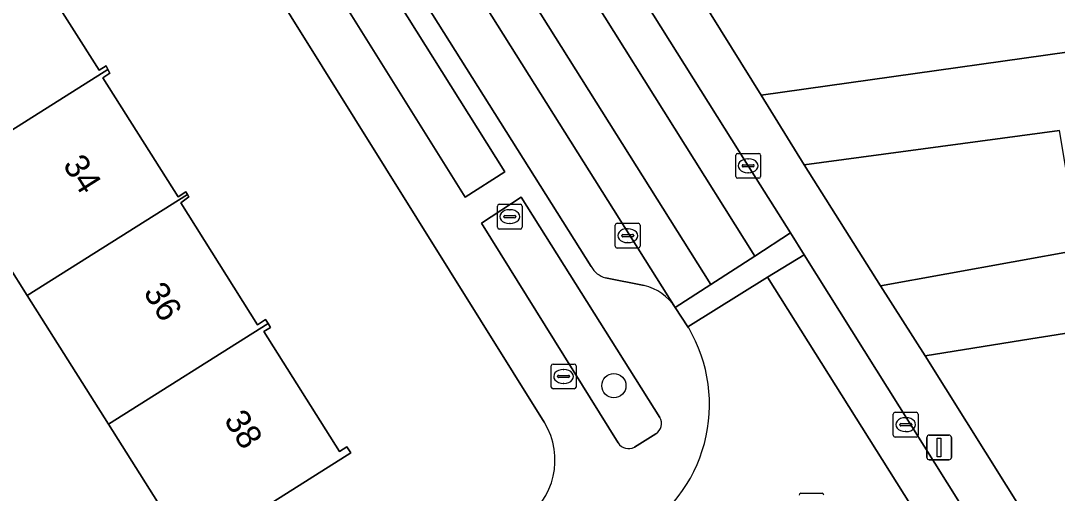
# Model space of a CAD drawing. Extents: x 160077 to 160948, y 386481 to 387498.
# Drawn here: x 160424.4 to 160466.22, y 387013.92 to 387032.98 of the extents above; entities that cross this region are included whole.
import ezdxf

# ---------------------------------------------------------------- set-up
doc = ezdxf.new("R2010")
doc.units = 0
for name, color, linetype in [('IMGEO_Boom', 7, 'Continuous'), ('IMGEO_Brandkraan', 7, 'Continuous'), ('IMGEO_Erf', 7, 'Continuous'), ('IMGEO_Groenvoorziening', 7, 'Continuous'), ('IMGEO_Kolk', 7, 'Continuous'), ('IMGEO_Lichtmast', 7, 'Continuous'), ('IMGEO_Pand', 7, 'Continuous'), ('IMGEO_Pand_nummerreeks', 7, 'Continuous'), ('IMGEO_Parkeervlak_open', 7, 'Continuous'), ('IMGEO_Rijbaan_lokaal_gesloten', 7, 'Continuous'), ('IMGEO_Rijbaan_lokaal_open', 7, 'Continuous'), ('IMGEO_Rioolput', 7, 'Continuous'), ('IMGEO_Voetpad_open', 7, 'Continuous')]:
    doc.layers.add(name, color=color, linetype=linetype)

msp = doc.modelspace()

# ---------------------------------------------------------------- linework, layer by layer
at = {"layer": 'IMGEO_Boom'}
msp.add_circle((160448.328, 387018.258), 0.489, dxfattribs=at)
at = {"layer": 'IMGEO_Brandkraan'}
for p, q in [((160445.799, 387018.204), (160445.799, 387019.056)), ((160445.874, 387019.13), (160446.726, 387019.13)), ((160446.287, 387018.91), (160446.312, 387018.91)), ((160446.8, 387019.056), (160446.8, 387018.204)), ((160446.058, 387018.624), (160446.058, 387018.636)), ((160446.496, 387018.587), (160446.098, 387018.587)), ((160446.101, 387018.673), (160446.499, 387018.673)), ((160446.542, 387018.636), (160446.542, 387018.624)), ((160446.726, 387018.13), (160445.874, 387018.13)), ((160446.31, 387018.35), (160446.285, 387018.35))]:
    msp.add_line(p, q, dxfattribs=at)
for points in [[(160445.799, 387018.204), (160445.799, 387019.056)], [(160445.874, 387019.13), (160446.726, 387019.13)], [(160446.8, 387019.056), (160446.8, 387018.204)], [(160446.726, 387018.13), (160445.874, 387018.13)]]:
    msp.add_lwpolyline(points, dxfattribs=at)
for centre, radius, start, end in [((160445.876, 387019.054), 0.0765, 91.552, 178.448), ((160445.876, 387019.054), 0.0765, 91.552, 178.448), ((160446.724, 387019.054), 0.0765, 1.552, 88.448), ((160446.724, 387019.054), 0.0765, 1.552, 88.448), ((160446.098, 387018.633), 0.0403, 85.8775, 175.7526), ((160446.095, 387018.623), 0.0366, 178.938, 274.7102), ((160446.499, 387018.63), 0.043, 264.8664, 352.4533), ((160446.503, 387018.635), 0.0386, 1.7309, 96.639), ((160445.876, 387018.206), 0.0765, 181.552, 268.448), ((160445.876, 387018.206), 0.0765, 181.552, 268.448), ((160446.724, 387018.206), 0.0765, 271.552, 358.448), ((160446.724, 387018.206), 0.0765, 271.552, 358.448)]:
    msp.add_arc(centre, radius, start, end, dxfattribs=at)
for centre, major_axis, ratio, start_param, end_param in [((160446.286, 387018.63), (-0.387, 0.002), 0.722429, 4.712389, 7.853982), ((160446.311, 387018.63), (-0.39, 0.002), 0.717154, 1.570796, 4.712389)]:
    msp.add_ellipse(centre, major_axis=major_axis, ratio=ratio, start_param=start_param, end_param=end_param, dxfattribs=at)
at = {"layer": 'IMGEO_Erf'}
for points in [[(160436.293, 387058.867), (160454.264, 387029.968), (160471.096, 387032.344), (160516.497, 387039.629), (160514.932, 387049.194), (160513.761, 387056.353), (160520.499, 387057.388)], [(160445.527, 387016.772), (160445.519, 387016.785), (160423.783, 387051.6)], [(160424.447, 387035.907), (160427.556, 387030.979), (160427.84, 387031.158), (160427.914, 387031.009), (160427.989, 387030.859), (160427.713, 387030.674), (160430.743, 387025.872), (160431.058, 387026.07), (160431.119, 387025.971), (160431.178, 387025.874), (160430.851, 387025.634), (160433.953, 387020.718), (160434.276, 387020.922), (160434.375, 387020.765), (160434.473, 387020.61), (160434.202, 387020.439), (160437.253, 387015.604), (160437.555, 387015.794), (160437.712, 387015.544), (160431.243, 387011.463), (160427.937, 387016.702), (160424.66, 387021.895), (160421.473, 387026.944)]]:
    msp.add_lwpolyline(points, dxfattribs=at)
msp.add_arc((160443.038, 387015.255), 2.915, 302.8254, 31.3564, dxfattribs=at)
at = {"layer": 'IMGEO_Groenvoorziening'}
for points in [[(160438.184, 387036.037), (160436.613, 387035.011), (160442.33, 387025.857), (160443.932, 387026.885)], [(160466.313, 387028.547), (160456.003, 387027.165), (160459.086, 387022.289), (160467.115, 387023.735)]]:
    msp.add_lwpolyline(points, close=True, dxfattribs=at)
for points in [[(160536.126, 387031.222), (160522.827, 387029.176), (160500, 387025.661), (160465.147, 387020.143), (160460.883, 387019.457), (160464.986, 387012.914)], [(160444.582, 387025.864), (160442.985, 387024.818), (160448.503, 387015.949)], [(160450.181, 387016.975), (160444.582, 387025.864)], [(160449.155, 387015.781), (160450.02, 387016.321)]]:
    msp.add_lwpolyline(points, dxfattribs=at)
for centre, radius, start, end in [((160449.782, 387016.726), 0.47, 300.4166, 31.9236), ((160448.917, 387016.205), 0.487, 211.7671, 299.3349)]:
    msp.add_arc(centre, radius, start, end, dxfattribs=at)
at = {"layer": 'IMGEO_Kolk'}
for p, q in [((160453.247, 387026.699), (160453.247, 387027.551)), ((160453.322, 387027.625), (160454.174, 387027.625)), ((160453.735, 387027.405), (160453.76, 387027.405)), ((160454.248, 387027.551), (160454.248, 387026.699)), ((160453.506, 387027.119), (160453.506, 387027.131)), ((160453.944, 387027.082), (160453.546, 387027.082)), ((160453.549, 387027.168), (160453.947, 387027.168)), ((160453.99, 387027.131), (160453.99, 387027.119)), ((160454.174, 387026.625), (160453.322, 387026.625)), ((160453.758, 387026.845), (160453.733, 387026.845)), ((160443.627, 387024.65), (160443.627, 387025.502)), ((160443.702, 387025.576), (160444.554, 387025.576)), ((160444.115, 387025.356), (160444.14, 387025.356)), ((160444.628, 387025.502), (160444.628, 387024.65)), ((160443.886, 387025.07), (160443.886, 387025.082)), ((160444.324, 387025.033), (160443.926, 387025.033)), ((160443.929, 387025.119), (160444.327, 387025.119)), ((160444.138, 387024.796), (160444.113, 387024.796)), ((160444.37, 387025.082), (160444.37, 387025.07)), ((160448.461, 387024.807), (160449.313, 387024.807)), ((160444.554, 387024.576), (160443.702, 387024.576)), ((160448.386, 387023.881), (160448.386, 387024.733)), ((160448.688, 387024.35), (160449.086, 387024.35)), ((160448.874, 387024.587), (160448.899, 387024.587)), ((160449.387, 387024.733), (160449.387, 387023.881)), ((160448.645, 387024.301), (160448.645, 387024.313)), ((160449.083, 387024.264), (160448.685, 387024.264)), ((160448.897, 387024.027), (160448.872, 387024.027)), ((160449.129, 387024.313), (160449.129, 387024.301)), ((160449.313, 387023.807), (160448.461, 387023.807)), ((160459.601, 387016.26), (160459.601, 387017.112)), ((160459.676, 387017.186), (160460.528, 387017.186)), ((160460.089, 387016.966), (160460.114, 387016.966)), ((160460.602, 387017.112), (160460.602, 387016.26)), ((160459.86, 387016.68), (160459.86, 387016.692)), ((160460.298, 387016.643), (160459.9, 387016.643)), ((160459.903, 387016.729), (160460.301, 387016.729)), ((160460.112, 387016.406), (160460.087, 387016.406)), ((160460.344, 387016.692), (160460.344, 387016.68)), ((160460.528, 387016.186), (160459.676, 387016.186))]:
    msp.add_line(p, q, dxfattribs=at)
for points in [[(160453.247, 387026.699), (160453.247, 387027.551)], [(160453.322, 387027.625), (160454.174, 387027.625)], [(160454.248, 387027.551), (160454.248, 387026.699)], [(160454.174, 387026.625), (160453.322, 387026.625)], [(160443.627, 387024.65), (160443.627, 387025.502)], [(160443.702, 387025.576), (160444.554, 387025.576)], [(160444.628, 387025.502), (160444.628, 387024.65)], [(160448.461, 387024.807), (160449.313, 387024.807)], [(160444.554, 387024.576), (160443.702, 387024.576)], [(160448.386, 387023.881), (160448.386, 387024.733)], [(160449.387, 387024.733), (160449.387, 387023.881)], [(160449.313, 387023.807), (160448.461, 387023.807)], [(160459.601, 387016.26), (160459.601, 387017.112)], [(160459.676, 387017.186), (160460.528, 387017.186)], [(160460.602, 387017.112), (160460.602, 387016.26)], [(160460.528, 387016.186), (160459.676, 387016.186)]]:
    msp.add_lwpolyline(points, dxfattribs=at)
for centre, radius, start, end in [((160453.324, 387027.549), 0.0765, 91.552, 178.448), ((160453.324, 387027.549), 0.0765, 91.552, 178.448), ((160454.172, 387027.549), 0.0765, 1.552, 88.448), ((160454.172, 387027.549), 0.0765, 1.552, 88.448), ((160453.546, 387027.128), 0.0403, 85.8775, 175.7526), ((160453.543, 387027.118), 0.0366, 178.938, 274.7102), ((160453.947, 387027.125), 0.043, 264.8664, 352.4533), ((160453.951, 387027.13), 0.0386, 1.7309, 96.639), ((160453.324, 387026.701), 0.0765, 181.552, 268.448), ((160453.324, 387026.701), 0.0765, 181.552, 268.448), ((160454.172, 387026.701), 0.0765, 271.552, 358.448), ((160454.172, 387026.701), 0.0765, 271.552, 358.448), ((160443.704, 387025.5), 0.0765, 91.552, 178.448), ((160443.704, 387025.5), 0.0765, 91.552, 178.448), ((160444.552, 387025.5), 0.0765, 1.552, 88.448), ((160444.552, 387025.5), 0.0765, 1.552, 88.448), ((160443.926, 387025.079), 0.0403, 85.8775, 175.7526), ((160443.923, 387025.069), 0.0366, 178.938, 274.7102), ((160444.327, 387025.076), 0.043, 264.8664, 352.4533), ((160444.331, 387025.081), 0.0386, 1.7309, 96.639), ((160448.463, 387024.731), 0.0765, 91.552, 178.448), ((160448.463, 387024.731), 0.0765, 91.552, 178.448), ((160449.311, 387024.731), 0.0765, 1.552, 88.448), ((160449.311, 387024.731), 0.0765, 1.552, 88.448), ((160443.704, 387024.652), 0.0765, 181.552, 268.448), ((160443.704, 387024.652), 0.0765, 181.552, 268.448), ((160444.552, 387024.652), 0.0765, 271.552, 358.448), ((160444.552, 387024.652), 0.0765, 271.552, 358.448), ((160448.685, 387024.31), 0.0403, 85.8775, 175.7526), ((160449.09, 387024.312), 0.0386, 1.7309, 96.639), ((160448.682, 387024.3), 0.0366, 178.938, 274.7102), ((160449.086, 387024.307), 0.043, 264.8664, 352.4533), ((160448.463, 387023.883), 0.0765, 181.552, 268.448), ((160448.463, 387023.883), 0.0765, 181.552, 268.448), ((160449.311, 387023.883), 0.0765, 271.552, 358.448), ((160449.311, 387023.883), 0.0765, 271.552, 358.448), ((160459.678, 387017.11), 0.0765, 91.552, 178.448), ((160459.678, 387017.11), 0.0765, 91.552, 178.448), ((160460.526, 387017.11), 0.0765, 1.552, 88.448), ((160460.526, 387017.11), 0.0765, 1.552, 88.448), ((160459.9, 387016.689), 0.0403, 85.8775, 175.7526), ((160459.897, 387016.679), 0.0366, 178.938, 274.7102), ((160460.301, 387016.686), 0.043, 264.8664, 352.4533), ((160460.305, 387016.691), 0.0386, 1.7309, 96.639), ((160459.678, 387016.262), 0.0765, 181.552, 268.448), ((160459.678, 387016.262), 0.0765, 181.552, 268.448), ((160460.526, 387016.262), 0.0765, 271.552, 358.448), ((160460.526, 387016.262), 0.0765, 271.552, 358.448)]:
    msp.add_arc(centre, radius, start, end, dxfattribs=at)
for centre, major_axis, ratio, start_param, end_param in [((160453.734, 387027.125), (-0.387, 0.002), 0.722429, 4.712389, 7.853982), ((160453.759, 387027.125), (-0.39, 0.002), 0.717154, 1.570796, 4.712389), ((160444.114, 387025.076), (-0.387, 0.002), 0.722429, 4.712389, 7.853982), ((160444.139, 387025.076), (-0.39, 0.002), 0.717154, 1.570796, 4.712389), ((160448.873, 387024.307), (-0.387, 0.002), 0.722429, 4.712389, 7.853982), ((160448.898, 387024.307), (-0.39, 0.002), 0.717154, 1.570796, 4.712389), ((160460.088, 387016.686), (-0.387, 0.002), 0.722429, 4.712389, 7.853982), ((160460.113, 387016.686), (-0.39, 0.002), 0.717154, 1.570796, 4.712389)]:
    msp.add_ellipse(centre, major_axis=major_axis, ratio=ratio, start_param=start_param, end_param=end_param, dxfattribs=at)
at = {"layer": 'IMGEO_Lichtmast'}
for p, q in [((160460.954, 387015.366), (160460.954, 387016.166)), ((160460.954, 387016.166), (160460.954, 387015.366)), ((160461.054, 387016.266), (160461.844, 387016.266)), ((160461.844, 387016.266), (160461.054, 387016.266)), ((160461.944, 387016.166), (160461.944, 387015.366)), ((160461.944, 387015.366), (160461.944, 387016.166)), ((160461.844, 387015.266), (160461.054, 387015.266)), ((160461.054, 387015.266), (160461.844, 387015.266))]:
    msp.add_line(p, q, dxfattribs=at)
msp.add_lwpolyline([(160461.374, 387016.141), (160461.524, 387016.141), (160461.524, 387015.391), (160461.374, 387015.391), (160461.374, 387016.141)], dxfattribs=at)
for centre, start, end in [((160461.054, 387016.166), 90, 180), ((160461.054, 387016.166), 90, 180), ((160461.844, 387016.166), 0, 90), ((160461.844, 387016.166), 360, 90), ((160461.054, 387015.366), 180, 270), ((160461.054, 387015.366), 180, 270), ((160461.844, 387015.366), 270, 0), ((160461.844, 387015.366), 270, 0)]:
    msp.add_arc(centre, 0.1, start, end, dxfattribs=at)
at = {"layer": 'IMGEO_Pand'}
for points in [[(160418.212, 387032.112), (160421.473, 387026.944), (160427.914, 387031.009), (160427.84, 387031.158), (160427.556, 387030.979), (160424.447, 387035.907), (160424.705, 387036.07), (160424.642, 387036.17)], [(160431.119, 387025.971), (160431.058, 387026.07), (160430.743, 387025.872), (160427.713, 387030.674), (160427.989, 387030.859), (160427.914, 387031.009), (160421.473, 387026.944), (160424.66, 387021.895)], [(160434.375, 387020.765), (160434.276, 387020.922), (160433.953, 387020.718), (160430.851, 387025.634), (160431.178, 387025.874), (160431.119, 387025.971), (160424.66, 387021.895), (160427.937, 387016.702)], [(160427.937, 387016.702), (160431.243, 387011.463), (160437.712, 387015.544), (160437.555, 387015.794), (160437.253, 387015.604), (160434.202, 387020.439), (160434.473, 387020.61), (160434.375, 387020.765)]]:
    msp.add_lwpolyline(points, close=True, dxfattribs=at)
at = {"layer": 'IMGEO_Parkeervlak_open'}
for points in [[(160450.802, 387021.407), (160429.818, 387054.758)], [(160429.809, 387051.026), (160447.411, 387023.059)], [(160447.989, 387022.61), (160449.549, 387022.299)]]:
    msp.add_lwpolyline(points, dxfattribs=at)
for centre, radius, start, end in [((160448.226, 387023.511), 0.932, 209.0415, 255.2772), ((160449.063, 387020.29), 2.067, 32.71, 76.3965)]:
    msp.add_arc(centre, radius, start, end, dxfattribs=at)
at = {"layer": 'IMGEO_Rijbaan_lokaal_gesloten'}
for points in [[(160416.063, 387087.072), (160406.823, 387101.852), (160398.089, 387115.794), (160388.289, 387131.421), (160386.556, 387134.162), (160385.146, 387133.284), (160405.388, 387100.925), (160454.017, 387023.48), (160455.457, 387024.416), (160453.748, 387027.125), (160445.805, 387039.762), (160436.736, 387054.149), (160431.311, 387062.749), (160427.037, 387069.523), (160425.845, 387071.435)], [(160383.315, 387132.149), (160381.898, 387131.264), (160382.171, 387130.783), (160398.645, 387104.519), (160401.279, 387100.695), (160425.761, 387061.225), (160426.837, 387059.5), (160429.508, 387055.263), (160429.818, 387054.758), (160450.802, 387021.407), (160452.236, 387022.341), (160427.331, 387061.943), (160402.73, 387101.168), (160393.07, 387116.568)], [(160454.532, 387022.633), (160456.003, 387023.539), (160455.457, 387024.416), (160454.017, 387023.48), (160452.236, 387022.341), (160450.802, 387021.407), (160451.315, 387020.631)], [(160456.003, 387023.539), (160454.532, 387022.633), (160464.671, 387006.514), (160466.121, 387007.413)]]:
    msp.add_lwpolyline(points, close=True, dxfattribs=at)
at = {"layer": 'IMGEO_Rijbaan_lokaal_open'}
msp.add_lwpolyline([(160405.388, 387100.925), (160385.146, 387133.284), (160383.315, 387132.149), (160393.07, 387116.568), (160402.73, 387101.168), (160427.331, 387061.943), (160452.236, 387022.341), (160454.017, 387023.48)], close=True, dxfattribs=at)
for points in [[(160454.532, 387022.633), (160451.315, 387020.631), (160451.345, 387020.586)], [(160461.463, 387004.46), (160464.671, 387006.514), (160454.532, 387022.633)]]:
    msp.add_lwpolyline(points, dxfattribs=at)
msp.add_arc((160446.083, 387017.498), 6.102, 299.8554, 30.4053, dxfattribs=at)
at = {"layer": 'IMGEO_Rioolput'}
msp.add_line((160455.874, 387013.918), (160456.726, 387013.918), dxfattribs=at)
msp.add_lwpolyline([(160455.874, 387013.918), (160456.726, 387013.918)], dxfattribs=at)
for centre, start, end in [((160455.876, 387013.842), 91.552, 178.448), ((160455.876, 387013.842), 91.552, 178.448), ((160456.724, 387013.842), 1.552, 88.448), ((160456.724, 387013.842), 1.552, 88.448)]:
    msp.add_arc(centre, 0.0765, start, end, dxfattribs=at)
at = {"layer": 'IMGEO_Voetpad_open'}
for points in [[(160375.529, 387128.679), (160377.667, 387125.214), (160378.372, 387124.087), (160421.163, 387055.706), (160423.783, 387051.6), (160445.519, 387016.785), (160445.527, 387016.772)], [(160464.986, 387012.914), (160460.883, 387019.457), (160459.086, 387022.289), (160456.003, 387027.165), (160454.264, 387029.968), (160436.293, 387058.867), (160436.241, 387058.827), (160426.893, 387073.762), (160426.9, 387073.769), (160411.212, 387098.821)], [(160416.063, 387087.072), (160425.845, 387071.435), (160427.037, 387069.523), (160427.914, 387070.081), (160432.188, 387063.326), (160431.311, 387062.749), (160436.736, 387054.149), (160445.805, 387039.762), (160453.748, 387027.125), (160455.457, 387024.416), (160456.003, 387023.539), (160466.121, 387007.413)], [(160447.411, 387023.059), (160429.809, 387051.026)], [(160471.096, 387032.344), (160454.264, 387029.968), (160456.003, 387027.165), (160466.313, 387028.547)], [(160448.503, 387015.949), (160442.985, 387024.818), (160444.582, 387025.864), (160450.181, 387016.975)], [(160467.115, 387023.735), (160459.086, 387022.289), (160460.883, 387019.457), (160465.147, 387020.143), (160500, 387025.661)], [(160449.549, 387022.299), (160447.989, 387022.61)], [(160451.345, 387020.586), (160451.315, 387020.631), (160450.802, 387021.407)], [(160450.02, 387016.321), (160449.155, 387015.781)]]:
    msp.add_lwpolyline(points, dxfattribs=at)
msp.add_lwpolyline([(160436.613, 387035.011), (160438.184, 387036.037), (160443.932, 387026.885), (160442.33, 387025.857)], close=True, dxfattribs=at)
for centre, radius, start, end in [((160448.226, 387023.511), 0.932, 209.0415, 255.2772), ((160449.063, 387020.29), 2.067, 32.71, 76.3965), ((160446.083, 387017.498), 6.102, 299.8554, 30.4053), ((160449.782, 387016.726), 0.47, 300.4166, 31.9236), ((160443.038, 387015.255), 2.915, 302.8254, 31.3564), ((160448.917, 387016.205), 0.487, 211.7671, 299.3349)]:
    msp.add_arc(centre, radius, start, end, dxfattribs=at)

# ---------------------------------------------------------------- texts
at = {"layer": 'IMGEO_Pand_nummerreeks'}
for s, p in [('34', (160426.071, 387027.167)), ('36', (160429.321, 387022.021)), ('38', (160432.573, 387016.872))]:
    msp.add_text(s, height=1, rotation=302.2761, dxfattribs=at).set_placement(p)

doc.saveas('drawing.dxf')
